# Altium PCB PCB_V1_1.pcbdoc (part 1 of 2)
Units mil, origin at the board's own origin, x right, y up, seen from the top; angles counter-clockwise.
Board outline 2047.24 x 3937.01 mil, 2 copper layers (Top Layer, Bottom Layer), stack 62.206 mil thick; 99 components, 62 nets, 329 pads, 46 vias.
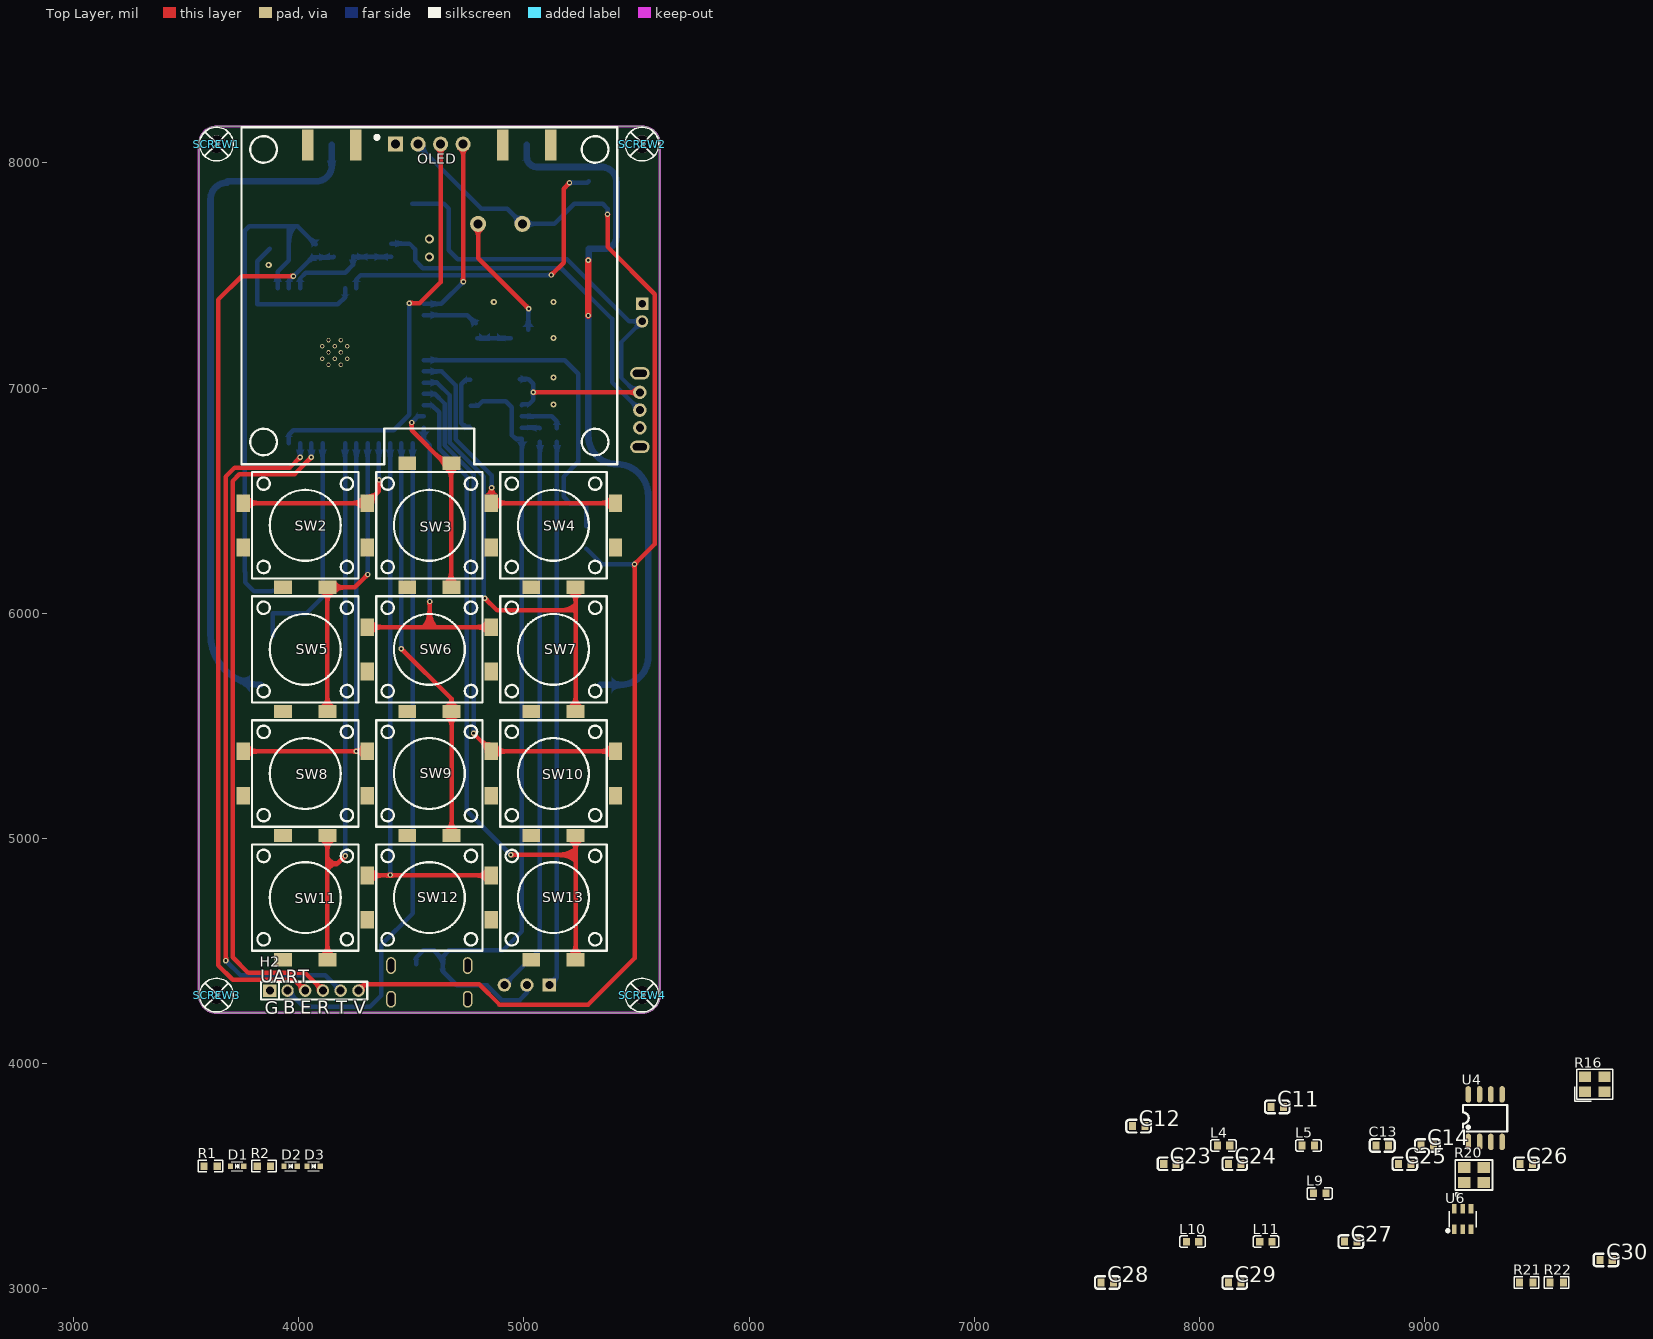
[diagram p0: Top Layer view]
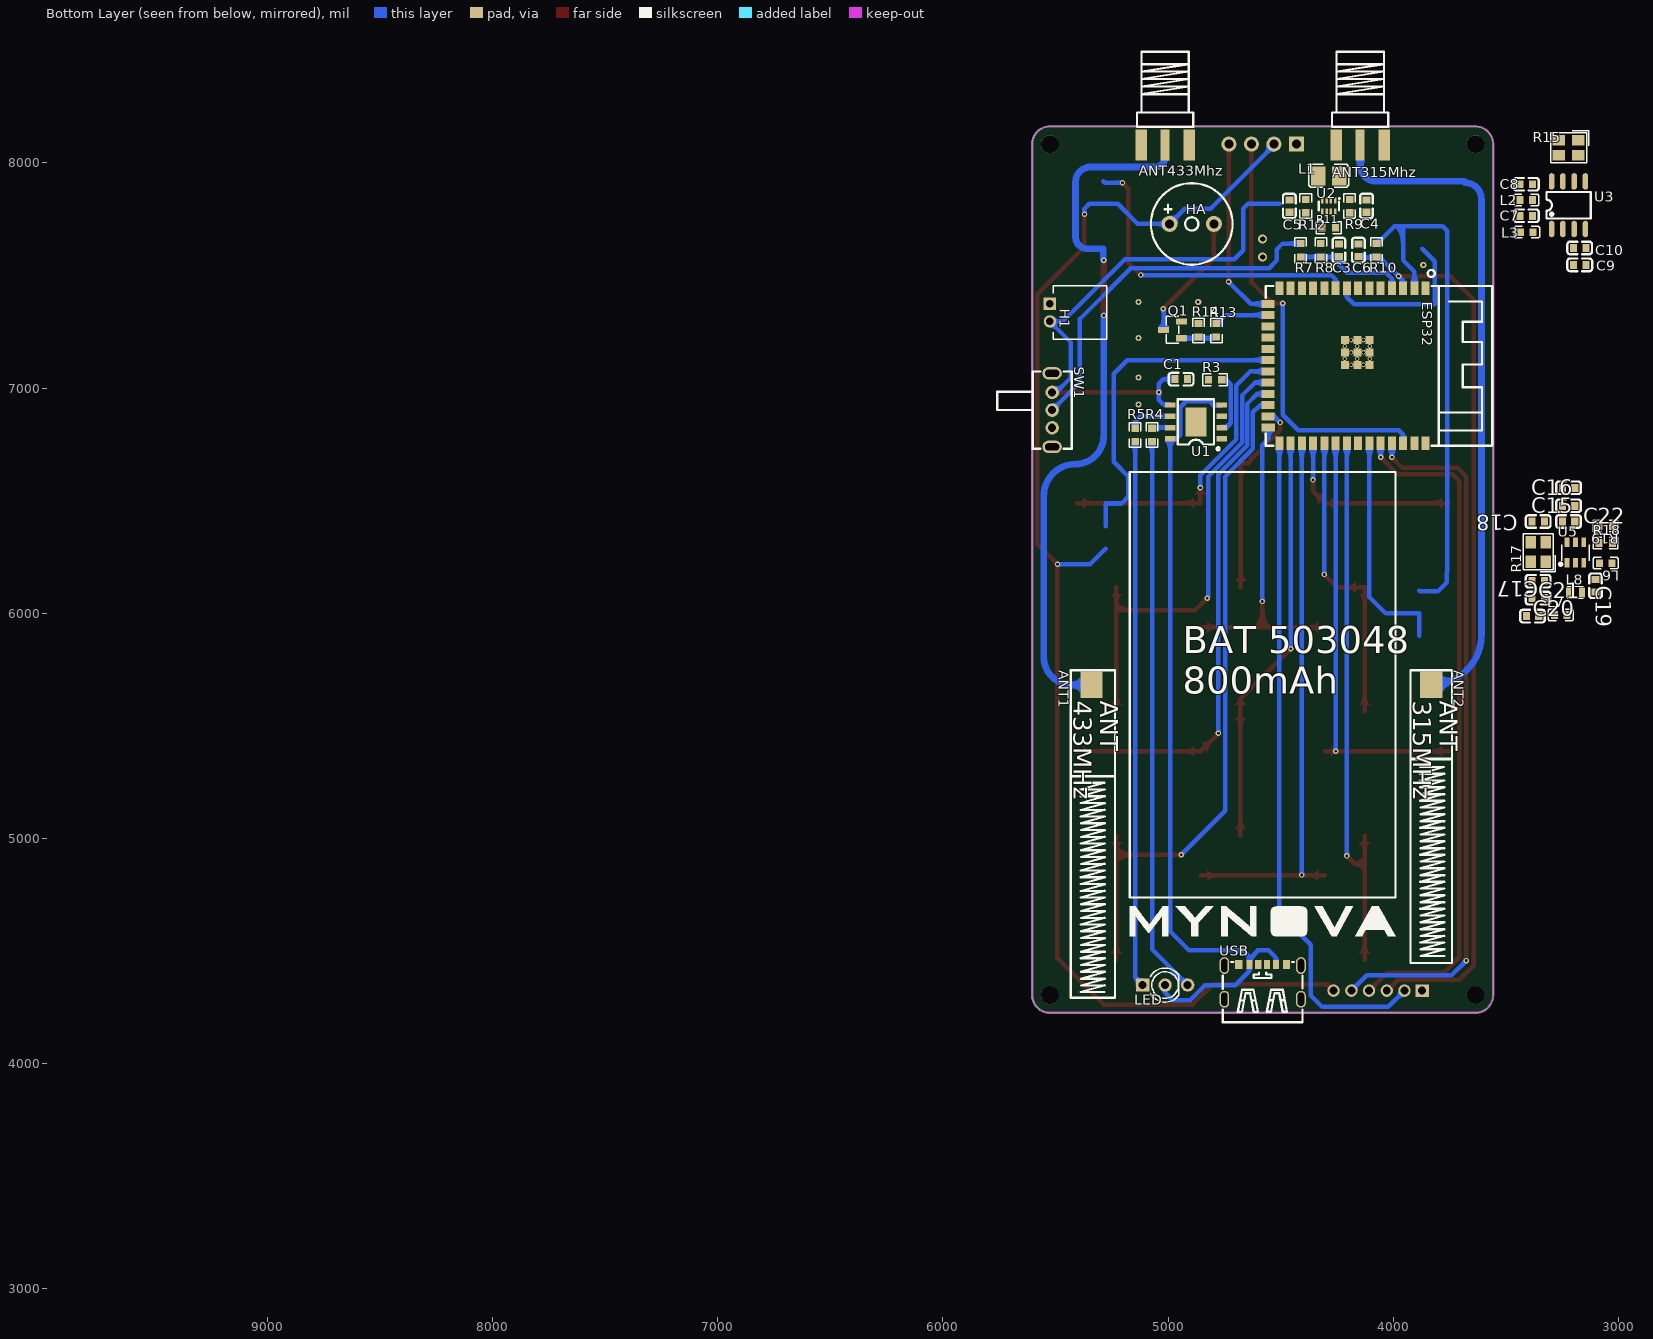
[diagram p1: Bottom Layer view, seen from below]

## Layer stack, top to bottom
Top Solder Mask Layer: solder mask 0.394, Dk 3.3
Top Layer: signal copper 1.379
Dielectric1: surface 59.449, FR4, Dk 4.5
Bottom Layer: signal copper 1.378
Bottom Solder Mask Layer: solder mask 0.394, Dk 3.3

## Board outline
3556.07,4304.21 ccw(c3634.81,4304.21) 3634.81,4225.47 5524.57,4225.47 ccw(c5524.57,4304.21) 5603.31,4304.21 5603.31,8083.74 ccw(c5524.57,8083.74) 5524.57,8162.48 3634.81,8162.48 ccw(c3634.81,8083.74) 3556.07,8083.74

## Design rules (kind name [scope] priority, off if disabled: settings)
BoardOutlineClearance copperThickness1oz [All] p0: genericclearance=10 ignorepadtopadclearanceinfootprint=FALSE except(0: Arc-SplitContinuation Track-SplitContinuation SMDPad-SplitContinuation THPad-SplitContinuation Via-SplitContinuation Fill-SplitContinuation Poly-SplitContinuation Region-SplitContinuation Text-SplitContinuation)
BoardOutlineClearance copperThickness2oz [All] p0: genericclearance=10 ignorepadtopadclearanceinfootprint=FALSE except(0: Arc-SplitContinuation Track-SplitContinuation SMDPad-SplitContinuation THPad-SplitContinuation Via-SplitContinuation Fill-SplitContinuation Poly-SplitContinuation Region-SplitContinuation Text-SplitContinuation)
BoardOutlineClearance Plane_innerPlane [All] p0: genericclearance=10 ignorepadtopadclearanceinfootprint=FALSE except(0: Arc-SplitContinuation Track-SplitContinuation SMDPad-SplitContinuation THPad-SplitContinuation Via-SplitContinuation Fill-SplitContinuation Poly-SplitContinuation Region-SplitContinuation Text-SplitContinuation)
BoardOutlineClearance Copper_copperRegion [All] p0: genericclearance=10 ignorepadtopadclearanceinfootprint=FALSE except(0: Arc-SplitContinuation Track-SplitContinuation SMDPad-SplitContinuation THPad-SplitContinuation Via-SplitContinuation Fill-SplitContinuation Poly-SplitContinuation Region-SplitContinuation Text-SplitContinuation)
BoardOutlineClearance Copper_Direct [All] p0: genericclearance=10 ignorepadtopadclearanceinfootprint=FALSE except(0: Arc-SplitContinuation Track-SplitContinuation SMDPad-SplitContinuation THPad-SplitContinuation Via-SplitContinuation Fill-SplitContinuation Poly-SplitContinuation Region-SplitContinuation Text-SplitContinuation)
BoardOutlineClearance otherClearance [All] p0: genericclearance=10 ignorepadtopadclearanceinfootprint=FALSE except(0: Arc-SplitContinuation Track-SplitContinuation SMDPad-SplitContinuation THPad-SplitContinuation Via-SplitContinuation Fill-SplitContinuation Poly-SplitContinuation Region-SplitContinuation Text-SplitContinuation)
Clearance copperThickness1oz [All] p1: gap=7 ignorepadtopadclearanceinfootprint=FALSE
Clearance copperThickness2oz [All] p1: gap=7 ignorepadtopadclearanceinfootprint=FALSE
Clearance Plane_innerPlane [All] p1: gap=7 ignorepadtopadclearanceinfootprint=FALSE
Clearance Copper_copperRegion [All] p1: gap=7 ignorepadtopadclearanceinfootprint=FALSE
Clearance Copper_Direct [All] p1: gap=7 ignorepadtopadclearanceinfootprint=FALSE
Clearance otherClearance [All] p1: gap=7 ignorepadtopadclearanceinfootprint=FALSE
DiffPairsRouting differentialPair [All] p1: maxuncoupledlength=10 minlimit=5.9843 maxlimit=Infinity mostfreqgap=5.9843 toplayer_minwidth=5 toplayer_prefwidth=10 toplayer_maxwidth=100 bottomlayer_minwidth=5 bottomlayer_prefwidth=10 bottomlayer_maxwidth=100
PasteMaskExpansion pasteMaskExpansion [All] p1: expansion=0
PlaneConnect innerPlane [All] p1: planeconnectstyle=Relief reliefexpansion=20 reliefentries=4 reliefconductorwidth=10 reliefairgap=10
PolygonConnect copperRegion [All] p1: connectstyle=Relief reliefentries=4 reliefconductorwidth=10 polygonreliefangle="90 Angle" airgapwidth=10
PolygonConnect Direct [All] p1: connectstyle=Direct reliefentries=4 reliefconductorwidth=10 polygonreliefangle="90 Angle" airgapwidth=10
RoutingVias viaSize [All] p1: viastyle="Through Hole" holewidth=12.0078 minholewidth=11.811 maxholewidth=248.0314 width=12.0078 minwidth=11.811 maxwidth=248.0314
SolderMaskExpansion solderMaskExpansion [All] p1: useseparateexpansions=TRUE expansion=2.0079 expansionbottom=2.0079
Width copperThickness1oz [All] p1: maxlimit=100 minlimit=5 preferedwidth=10
Width copperThickness2oz [All] p1: maxlimit=100 minlimit=8 preferedwidth=10

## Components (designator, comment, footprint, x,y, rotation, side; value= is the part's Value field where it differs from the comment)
ANT1 "" SMD-ANT-433 5339.53,5682.17 r270 bottom
ANT2 "" SMD-ANT-315 3831.07,5682.17 r270 bottom
ANT315Mhz "" SMA-TH_SMA-KE-P901 4146.62,8079.8 r180 bottom
ANT433Mhz "" SMA-TH_SMA-KE-P901 5012.76,8079.8 r180 bottom
C1 "" C0603 4941.92,7039.76 r180 bottom
C3 "" C0603 4241.07,7612.48 r270 bottom
C4 "" C0603 4118.56,7808.82 r90 bottom
C5 "" C0603 4461.07,7808.82 r90 bottom
C6 "" C0603 4154.4,7612.48 r270 bottom
C7 "" C0603 3408.55,7765.65 r180 bottom
C8 "" C0603 3408.55,7905.65 r180 bottom
C9 "" C0603 3171.68,7547.69 r0 bottom
C10 "" C0603 3171.68,7622.69 r0 bottom
C11 "" C0603 8345.53,3807.83 r0 top
C12 "" C0603 7730.1,3722.23 r0 top
C13 "" C0603 8812.23,3636.43 r0 top
C14 "" C0603 9012.23,3636.43 r0 top
C15 "" C0603 3221.07,6477.48 r0 bottom
C16 "" C0603 3221.07,6557.48 r0 bottom
C17 "" C0603 3356.07,6142.48 r0 bottom
C18 "" C0603 3356.07,6407.48 r0 bottom
C19 "" C0603 3101.07,6122.48 r270 bottom
C20 "" C0603 3381.07,5987.48 r180 bottom
C21 "" C0603 3356.07,6067.48 r180 bottom
C22 "" C0603 3221.07,6407.48 r180 bottom
C23 "" C0603 7869.24,3555.14 r0 top
C24 "" C0603 8157.06,3555.14 r0 top
C25 "" C0603 8912.23,3555.14 r0 top
C26 "" C0603 9451.97,3555.14 r0 top
C27 "" C0603 8672.49,3209.24 r0 top
C28 "" C0603 7590.97,3027.95 r0 top
C29 "" C0603 8157.06,3027.95 r0 top
C30 "" C0603 9805.8,3127.95 r0 top
D1 "" SOD-523_L1.2-W0.8-LS1.6-BI 3726.29,3544.64 r0 top
D2 "" SOD-523_L1.2-W0.8-LS1.6-BI 3963.39,3544.64 r0 top
D3 "" SOD-523_L1.2-W0.8-LS1.6-BI 4065.75,3544.64 r0 top
ESP32 "" WIRELM-SMD_ESP32-S3-WROOM-1 4205.67,7099.49 r270 bottom
H1 "" CONN-TH_PH-2AW_C2908634 5524.57,7335.71 r270 bottom
H2 "" 6PIN-2MM-UART 4067.88,4323.9 r0 top
HA "" BUZ-TH_BD9.0-P5.00-D0.6-FD 4894.65,7729.41 r180 bottom
L1 "" L1008 4286.07,7942.48 r180 bottom
L2 "" L0603 3408.55,7835.65 r0 bottom
L3 "" L0603 3406.07,7692.48 r180 bottom
L4 "" L0603 8107.06,3636.43 r0 top
L5 "" L0603 8484.01,3636.43 r0 top
L6 "" L0603 3056.07,6222.48 r0 bottom
L7 "" L0603 3256.07,5992.48 r180 bottom
L8 "" IND-SMD_L1.8-W1.1 3191.07,6092.48 r180 bottom
L9 "" L0603 8534.01,3423.91 r0 top
L10 "" L0603 7969.24,3209.24 r0 top
L11 "" L0603 8295.53,3209.24 r0 top
LED "" LED-TH_3P-BD3.8-P2.54-BI 5012.76,4348.9 r180 bottom
OLED "" OLED-TH_-4P-L42.4-W38.0-P2.54 4579.69,8083.74 r0 top
Q1 "" SOT-23-3_L2.9-W1.3-P1.90-LS2.4-BR 4980.01,7258.86 r180 bottom
R1 "" R0603 3607.73,3544.64 r0 top
R2 "" R0603 3844.84,3544.64 r0 top
R3 "" R0603 4791.07,7037.48 r180 bottom
R4 "" R0603 5071.07,6792.48 r90 bottom
R5 "" R0603 5146.07,6792.48 r90 bottom
R7 "" R0603 4411.07,7612.48 r90 bottom
R8 "" R0603 4321.07,7612.48 r270 bottom
R9 "" R0603 4193.56,7808.82 r90 bottom
R10 "" R0603 4074.4,7612.48 r270 bottom
R11 "" R0603 4286.07,7712.48 r180 bottom
R12 "" R0603 4388.56,7808.82 r90 bottom
R13 "" R0603 4785.09,7256.97 r270 bottom
R14 "" R0603 4864.37,7256.97 r90 bottom
R15 "" CRYSTAL-SMD_4P-L3.2-W2.5-BL 3221.07,8067.48 r0 bottom
R16 "" CRYSTAL-SMD_4P-L3.2-W2.5-BL 9755.8,3907.83 r0 top
R17 "" CRYSTAL-SMD_4P-L3.2-W2.5-BL 3356.07,6272.48 r90 bottom
R18 "" R0603 3056.07,6312.48 r180 bottom
R19 "" R0603 3056.07,6387.48 r0 bottom
R20 "" CRYSTAL-SMD_4P-L3.2-W2.5-BL_SIT8008BI 9219.14,3505.14 r0 top
R21 "" R0603 9451.97,3027.95 r0 top
R22 "" R0603 9586.71,3027.95 r0 top
SCREW1 "" M2螺丝 3634.81,8083.74 r0 top
SCREW2 "" M2螺丝 5524.57,8083.74 r0 top
SCREW3 "" M2螺丝 3634.81,4304.21 r0 top
SCREW4 "" M2螺丝 5524.57,4304.21 r0 top
SW1 "" SW-TH_SK12D07VG4 5514.57,6902.64 r270 bottom
SW2 "" SW-SMD_4P-L12.0-W12.0-P5.00-LS15.4 4028.51,6390.83 r0 top
SW3 "" SW-SMD_4P-L12.0-W12.0-P5.00-LS15.4 4579.69,6390.83 r270 top
SW4 "" SW-SMD_4P-L12.0-W12.0-P5.00-LS15.4 5130.87,6390.83 r0 top
SW5 "" SW-SMD_4P-L12.0-W12.0-P5.00-LS15.4 4028.51,5839.65 r270 top
SW6 "" SW-SMD_4P-L12.0-W12.0-P5.00-LS15.4 4579.69,5839.65 r0 top
SW7 "" SW-SMD_4P-L12.0-W12.0-P5.00-LS15.4 5130.87,5839.65 r270 top
SW8 "" SW-SMD_4P-L12.0-W12.0-P5.00-LS15.4 4028.51,5288.46 r0 top
SW9 "" SW-SMD_4P-L12.0-W12.0-P5.00-LS15.4 4579.69,5288.46 r270 top
SW10 "" SW-SMD_4P-L12.0-W12.0-P5.00-LS15.4 5130.87,5288.46 r0 top
SW11 "" SW-SMD_4P-L12.0-W12.0-P5.00-LS15.4 4028.51,4737.28 r270 top
SW12 "" SW-SMD_4P-L12.0-W12.0-P5.00-LS15.4 4579.69,4737.28 r0 top
SW13 "" SW-SMD_4P-L12.0-W12.0-P5.00-LS15.4 5130.87,4737.28 r270 top
U1 "" ESOP-8_L4.9-W3.9-P1.27-LS6.0-BL-EP 4876.02,6849.76 r90 bottom
U2 "" SOT-583-8_L2.1-W1.2-P0.50-LS1.6-BL 4286.07,7808.82 r0 bottom
U3 "" SOP-8_L4.9-W3.9-P1.27-LS6.0-BL 3221.07,7812.48 r180 bottom
U4 "" SOP-8_L4.9-W3.9-P1.27-LS6.0-BL 9269.14,3757.83 r0 top
U5 "" SOT-23-6_L2.9-W1.6-P0.95-LS2.8-BL 3190.62,6269.24 r180 bottom
U6 "" SOT-23-6_L2.9-W1.6-P0.95-LS2.8-BL 9169.14,3309.24 r0 top
USB "" TYPE-C-SMD_TYPE-C-6P 4579.69,4363.27 r180 bottom

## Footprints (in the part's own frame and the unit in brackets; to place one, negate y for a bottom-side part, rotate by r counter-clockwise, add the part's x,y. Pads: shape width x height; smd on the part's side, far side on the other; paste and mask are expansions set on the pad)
6PIN-2MM-UART [mm]
  round 1.4 hole 0.9: BOOT(-3,0) EN(-1,0) RXD(1,0) TXD(3,0) VCC(5,0)
  rect 1.524x1.4 hole 0.9: GND(-5,0)
  silkscreen extent -6,-1 6,1.02
BUZ-TH_BD9.0-P5.00-D0.6-FD [mm]
  round 1.8 hole 1 copper offset 0,0: 1(-2.5,0)
  round 1.8 hole 1: 2(2.5,0)
  silkscreen extent -4.6,-4.6 4.6,4.6
C0603 [mm]
  rect 0.8x0.9 smd: 1(-0.7,0) 2(0.7,0)
  silkscreen extent -1.41,-0.71 1.39,0.72
CONN-TH_PH-2AW_C2908634 [mm]
  rect 1.4x1.4 hole 0.85: 1(-1,0)
  round 1.4 hole 0.85: 2(1,0)
  silkscreen extent -3,0.4 3,6.4
CRYSTAL-SMD_4P-L3.2-W2.5-BL [mm]
  rect 1.4x1.2 smd: 1(-1.1,-0.85) 2(1.1,-0.85) 3(1.1,0.85) 4(-1.1,0.85)
  silkscreen extent -2.26,-1.91 2.03,1.68
CRYSTAL-SMD_4P-L3.2-W2.5-BL_SIT8008BI [mm]
  rect 1.4x1.2 smd: 1(-1.1,-0.85) 2(1.1,-0.85) 3(1.1,0.85) 4(-1.1,0.85)
  silkscreen extent -2.1,-2.35 2.1,1.7
ESOP-8_L4.9-W3.9-P1.27-LS6.0-BL-EP [mm]
  rect 0.6x1.2 smd: 1(-1.905,-2.908) 2(-0.635,-2.908) 3(0.635,-2.908) 4(1.905,-2.908) 5(1.905,2.908) 6(0.635,2.908) 7(-0.635,2.908) 8(-1.905,2.908)
  rect 3.3x2.4 smd: 9(0,0)
  silkscreen extent -3.2,-2.67 2.55,2.05
IND-SMD_L1.8-W1.1 [mm]
  rect 0.64x1.1 smd: 1(-0.75,0) 2(0.75,0)
  silkscreen extent -0.9,-0.71 0.9,0.71
L0603 [mm]
  rect 0.8x0.864 smd: 1(-0.7,0) 2(0.7,0)
  silkscreen extent -1.42,-0.65 1.42,0.65
L1008 [mm]
  rect 1.635x2.16 smd: 1(-1.168,0) 2(1.168,0)
  silkscreen extent -2.27,-1.27 2.27,1.3
LED-TH_3P-BD3.8-P2.54-BI [mm]
  rect 1.5x1.5 hole 0.9: 1(-2.54,0)
  round 1.5 hole 0.9: 2(0,0) 3(2.54,0)
  silkscreen extent -1.7,-1.92 1.54,1.92
M2螺丝 [mm]
  round 2 hole 2: 1(0,0)
  silkscreen extent -1.9,-1.9 1.9,1.9
OLED-TH_-4P-L42.4-W38.0-P2.54 [mm]
  rect 1.7x1.7 hole 1: 1(-3.81,0)
  round 1.7 hole 1: 2(-1.27,0) 3(1.27,0) 4(3.81,0)
  silkscreen extent -21.2,-36.1 21.2,1.91
R0603 [mil]
  rect 31.75x34.02 smd: 1(-29.66,0) 2(29.66,0)
  silkscreen extent -55,-26 55,26
SMA-TH_SMA-KE-P901 [mm]
  rect 1.3x3.5 smd: 1(-2.7,0) 2(2.7,0)
  rect 1.3x3.5 smd far side: 3(-2.7,0) 4(2.7,0)
  rect 1x3.5 smd: 5(0,0)
  silkscreen extent -3.17,2.03 3.18,10.53
SMD-ANT-315 [mm]
  rect 3x2.5 smd: 1(0,0)
  silkscreen extent -1.65,-2.35 31.38,2.35
SMD-ANT-433 [mm]
  rect 3x2.5 smd: 1(0,0)
  silkscreen extent -1.65,-2.35 35.29,2.65
SOD-523_L1.2-W0.8-LS1.6-BI [mm]
  rect 0.6x0.6 smd: 1(-0.75,0) 2(0.75,0)
  silkscreen extent -0.65,-0.5 0.65,0.5
SOP-8_L4.9-W3.9-P1.27-LS6.0-BL [mm]
  oval 0.63x1.865 smd: 1(-1.905,-2.682) 2(-0.635,-2.682) 3(0.635,-2.682) 4(1.905,-2.682) 5(1.905,2.682) 6(0.635,2.682) 7(-0.635,2.682) 8(-1.905,2.682)
  silkscreen extent -2.5,-1.5 2.5,1.48
SOT-23-3_L2.9-W1.3-P1.90-LS2.4-BR [mm]
  rect 1.25x0.7 smd: 1(1,-0.95) 2(1,0.95) 3(-1,0)
  silkscreen extent -0.73,-1.53 0.73,1.53
SOT-23-6_L2.9-W1.6-P0.95-LS2.8-BL [mil]
  rect 20.95x42.2 smd: 1(-37.4,-45.24) 2(0,-45.24) 3(37.4,-45.24) 4(37.4,45.24) 5(0,45.24) 6(-37.4,45.24)
  silkscreen extent -72,-57 61,35
SOT-583-8_L2.1-W1.2-P0.50-LS1.6-BL [mm]
  rect 0.28x0.68 smd: 1(-0.75,-0.64) 2(-0.25,-0.64) 3(0.25,-0.64) 4(0.75,-0.64) 5(0.75,0.64) 6(0.25,0.64) 7(-0.25,0.64) 8(-0.75,0.64)
  silkscreen extent -1.27,-0.93 1.14,0.51
SW-SMD_4P-L12.0-W12.0-P5.00-LS15.4 [mm]
  rect 1.5x2 smd: 1(-7,2.5) 2(7,2.5) 3(-7,-2.5) 4(7,-2.5)
  silkscreen extent -6,-6 6,6
SW-TH_SK12D07VG4 [mil]
  round 60 hole 36: 1(-78.74,0) 2(0,0) 3(78.74,0)
  oval 55.12x86.61 hole 31.5 slot 62.99 at 90 deg: 4(163.38,0) 5(-163.39,0)
  silkscreen extent -171,-244 171,87
TYPE-C-SMD_TYPE-C-6P [mm]
  oval 1.1x1.9 hole 0.7 slot 1.5 at 90 deg: 7(-4.32,-1.963) 7(-4.32,1.838) 7(4.32,-1.963) 7(4.32,1.838)
  rect 0.7x1 smd: A5(-0.5,1.963) A9(1.5,1.963) B5(0.5,1.963) B9(-1.5,1.963)
  rect 0.8x1 smd: A12(2.7,1.963) B12(-2.7,1.963)
  silkscreen extent -4.5,-4.56 4.5,2.24
WIRELM-SMD_ESP32-S3-WROOM-1 [mm]
  rect 1.5x0.9 smd: 1(-8.75,8.895) 2(-8.75,7.625) 3(-8.75,6.355) 4(-8.75,5.085) 5(-8.75,3.815) 6(-8.75,2.545) 7(-8.75,1.275) 8(-8.75,0.005) 9(-8.75,-1.265) 10(-8.75,-2.535) 11(-8.75,-3.805) 12(-8.75,-5.075) 13(-8.75,-6.345) 14(-8.75,-7.615) 27(8.75,-7.615) 28(8.75,-6.345) 29(8.75,-5.075) 30(8.75,-3.805) 31(8.75,-2.535) 32(8.75,-1.265) 33(8.75,0.005) 34(8.75,1.275) 35(8.75,2.545) 36(8.75,3.815) 37(8.75,5.085) 38(8.75,6.355) 39(8.75,7.625) 40(8.75,8.895)
  rect 0.9x1.5 smd: 15(-6.985,-8.895) 16(-5.715,-8.895) 17(-4.445,-8.895) 18(-3.175,-8.895) 19(-1.905,-8.895) 20(-0.635,-8.895) 21(0.635,-8.895) 22(1.905,-8.895) 23(3.175,-8.895) 24(4.445,-8.895) 25(5.715,-8.895) 26(6.985,-8.865)
  rect 0.9x0.9 smd: 41(-2.9,-0.225) 41(-2.9,1.175) 41(-2.9,2.575) 41(-1.5,-0.225) 41(-1.5,1.175) 41(-1.5,2.575) 41(-0.1,-0.225) 41(-0.1,1.175) 41(-0.1,2.575)
  silkscreen extent -10.82,-9.14 9.02,16.39

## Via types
v1: diameter 24.02, hole 12.01, Top Layer to Bottom Layer, 26 vias
v2: diameter 19.69, hole 11.81, Top Layer to Bottom Layer, 12 vias
v3: diameter 27.56, hole 13.78, Top Layer to Bottom Layer, 6 vias
v4: diameter 39.37, hole 23.62, Top Layer to Bottom Layer, 2 vias

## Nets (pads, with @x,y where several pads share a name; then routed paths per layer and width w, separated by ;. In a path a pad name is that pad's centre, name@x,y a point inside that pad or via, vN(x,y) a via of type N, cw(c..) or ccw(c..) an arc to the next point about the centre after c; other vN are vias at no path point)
315_RX: ESP32.35 U3.5 | length 1034.9
  Bottom Layer w20: 3883.37,5900.27 3883.37,6000.27 4033.86,6000.27 4105.48,6071.89 ESP32.35@4105.48,6755
315_TX: ESP32.34 | length 711.2
  Bottom Layer w20: 3871.03,7618.78 3816.07,7563.83 3816.07,7372.48 4173.51,7372.48 4205.48,7404.45 4205.48,7443.98
315ANT: ANT2.1 ANT315Mhz.5 C7.1 C8.1 C20.2 L2.2 L7.1 | length 3000.1
  Bottom Layer w29.53: ANT2.1@3831.07,5682.17 cw(c3831.07,5905.49) 3607.74,5905.49 3607.74,7839.15 cw(c3681.07,7839.15) 3681.07,7912.48 cw(c3687.37,7912.48) 3687.37,7918.78 4077.37,7918.78 ccw(c4077.37,7987.48) 4146.07,7987.48 4146.07,8079.25 cw(c4146.62,8079.25) ANT315Mhz.5@4146.62,8079.8
433_RX: ESP32.20 U4.5 | length 1496.3
  Bottom Layer w20: ESP32.20@4555.87,7124.49 5181.07,7124.49 5241.07,7064.49 5241.07,6672.48 5176.07,6607.48 5176.07,6517.48 5205.87,6487.68 5276.01,6487.68 5276.01,6387.68
433_TX: ESP32.21 | length 1444.7
  Top Layer w20: v1(5121.07,7502.48) 5176.07,7557.48 5176.07,7886.31 v1(5202.23,7912.48)
  Bottom Layer w20: 4255.48,7443.98 4255.48,7482.48 4275.48,7502.48 v1(5121.07,7502.48) ; v1(5202.23,7912.48) 5282.06,7912.48 5288.35,7918.78
433ANT: ANT1.1 ANT433Mhz.5 C11.2 C12.1 C28.1 L4.2 L10.1 | length 3159.4
  Top Layer w29.53: v1(5286.07,7322.48) v1(5286.07,7567.48)
  Bottom Layer w29.53: ANT433Mhz.5@5012.76,8079.8 5012.76,8025.79 ccw(c5056.07,8025.79) 5056.07,7982.48 5343.23,7982.48 cw(c5343.23,7914.64) 5411.07,7914.64 5411.07,7672.48 cw(c5357.36,7672.48) 5357.36,7618.78 5288.35,7618.78 5288.35,7569.77 v1(5286.07,7567.48) ; v1(5286.07,7322.48) 5286.07,6787.48 ccw(c5411.07,6787.48) 5411.07,6662.48 cw(c5411.07,6521.91) 5551.64,6521.91 5551.64,5805.91 cw(c5427.9,5805.91) 5427.9,5682.17 ANT1.1@5339.53,5682.17
$1N804: U1.2 | length 270.1
  Bottom Layer w20: 4761.41,7037.48 4741.07,7037.48 4721.07,7017.48 4721.07,6844.76 4741.07,6824.76 U1.2@4761.52,6824.76
$1N6847: U1.7 | length 81.6
  Bottom Layer w20: U1.7@4990.52,6824.76 5068.45,6824.76 5071.07,6822.14
$1N7056: LED.1 | length 2427.7
  Bottom Layer w20: LED.1@5112.76,4348.9 5146.07,4382.2 5146.07,6762.82
$1N7064: U1.6 | length 195.1
  Bottom Layer w20: U1.6@4990.52,6874.76 5123.79,6874.76 5146.07,6852.48 5146.07,6822.14
$1N11631: LED.3 | length 2479.5
  Bottom Layer w20: LED.3@4912.76,4348.9 5071.07,4507.2 5071.07,6762.82
$1N15750: HA.2 Q1.3 | length 564.4
  Top Layer w20: HA.2@4796.23,7729.41 4796.22,7577.32 v1(5021.07,7352.48)
  Bottom Layer w20: Q1.3@5019.38,7258.86 5019.38,7350.79 v1(5021.07,7352.48)
$1N15783: Q1.1 | length 148.1
  Bottom Layer w20: 4792.49,7221.46 Q1.1@4940.64,7221.46
$1N28849: D2.1 R2.1 USB.B5
$1N28850: D1.1 R1.1 USB.A5
$1N28865: R9.1 R11.2 U2.8
$1N28870: L1.2 U2.2
$1N28871: L1.1 U2.3
$1N28873: U2.5 U2.6
$2N3: R22.2 U6.4
$2N4: R19.2 U5.4
$2N9: C18.2 R17.3 U5.6
$2N10: C26.2 R20.3 U6.6
$2N13: C25.1 R20.1 U6.1
$2N14: C17.1 R17.1 U5.1
$2N23: C29.1 L10.2 L11.1
$2N24: C21.2 L7.2 L8.1
$2N25: C19.2 L8.2
$2N26: C27.2 L11.2
$2N27: C27.1 L9.2 U6.3
$2N28: C19.1 L6.2 U5.3
$2N38: C7.2 L3.2 U3.2
$2N39: C11.1 L5.2 U4.2
$2N57: R16.3 U4.8
$2N58: R15.3 U3.8
$2N59: R16.1 U4.7
$2N60: R15.1 U3.7
+3.3V: C4.2 C9.2 C10.2 C13.2 C14.2 C15.1 C16.1 C22.2 C23.1 C24.1 C30.2 ESP32.2 H2.VCC HA.1 L6.1 L9.1 OLED.2 R9.2 U2.1 U3.3 U4.3 U5.5 U6.5 | length 8452.2
  Top Layer w20: H2.VCC@4264.73,4323.9 4293.31,4352.48 4801.07,4352.48 4891.07,4262.48 5286.07,4262.48 5491.07,4467.48 v1(5491.07,6217.48) 5581.07,6307.48 5581.07,7417.48 5371.07,7627.48 v1(5371.07,7772.48)
  Bottom Layer w19.68: 3947.54,7718.78 3994.35,7718.78 4073.27,7639.86 4074.4,7639.86
  Bottom Layer w20: 3883.37,6100.27 3880.58,6097.48 3801.07,6097.48 3761.07,6137.48 3761.07,6182.48 3759.89,6183.66 3759.89,7698.78 3779.89,7718.78 3947.54,7718.78 3956.07,7710.26 3956.07,7567.48 3905.48,7516.89 ESP32.2@3905.48,7443.98 ; OLED.2@4529.69,8083.74 4529.69,8078.86 4811.07,7797.48 4925,7797.48 HA.1@4993.09,7729.41 5133.87,7729.41 5223.23,7818.78 5349.77,7818.78 5371.07,7797.48 v1(5371.07,7772.48) ; 5276.01,6287.68 5346.21,6217.48 v1(5491.07,6217.48)
ADC: C3.2 ESP32.39 | length 511.9
  Bottom Layer w19.68: 4005.48,7443.98 4005.48,7486.89 4031.07,7512.48 4206.07,7512.48 4241.07,7547.48 C3.2@4241.07,7584.92 4243.17,7582.82 4321.07,7582.82 4411.07,7582.82
B+: C1.1 H1.2 SW1.1 U1.5 | length 2418
  Top Layer w20: v1(5041.07,6981.38) SW1.1@5514.57,6981.38
  Bottom Layer w19.68: 4504.02,7819.83 4643.72,7819.83 4666.07,7797.48 4666.07,7612.48 4706.07,7572.48 5191.07,7572.48 5467.21,7296.34 H1.2@5524.57,7296.34
  Bottom Layer w20: C1.1@4981.29,7039.76 5021.07,7039.76 5041.07,7019.76 v1(5041.07,6981.38) 5041.07,6947.48 5021.07,6927.48 4993.24,6927.48 U1.5@4990.52,6924.76 ; SW1.1@5514.57,6981.38 5497.17,6981.38 5431.07,7047.48 5431.07,7202.84 H1.2@5524.57,7296.34
BOOT: ESP32.27 H2.BOOT | length 2976.9
  Bottom Layer w20: H2.BOOT@3949.77,4323.9 4021.19,4252.48 4316.07,4252.48 4366.07,4302.48 4366.07,4527.48 4505.48,4666.89 ESP32.27@4505.48,6755
BUZZER: ESP32.16 | length 244.3
  Bottom Layer w20: ESP32.16@4555.87,7324.49 4748.78,7324.49 4785.09,7288.18
EN: C6.2 ESP32.3 H2.EN | length 4043.6
  Top Layer w20: v1(3976.07,7497.48) 3746.07,7497.48 3641.07,7392.48 3641.07,4437.48 3706.07,4372.48 3979.93,4372.48 H2.EN@4028.51,4323.9
  Bottom Layer w19.68: v1(3976.07,7497.48) 4059.13,7580.54 4074.4,7580.54
  Bottom Layer w20: ESP32.3@3955.48,7443.98 3955.48,7476.89 v1(3976.07,7497.48) ; 4074.4,7580.54 4152.3,7580.54 C6.2@4154.4,7582.64
GND: ANT315Mhz.1 ANT315Mhz.2 ANT315Mhz.3 ANT315Mhz.4 ANT433Mhz.1 ANT433Mhz.2 ANT433Mhz.3 ANT433Mhz.4 C1.2 C3.1 C4.1 C5.1 C6.1 C8.2 C9.1 C10.1 C12.2 C13.1 C14.1 C15.2 C16.2 C17.2 C18.1 C20.1 C21.1 C22.1 C23.2 C24.2 C25.2 C26.1 C28.2 C29.2 C30.1 D1.2 D2.2 D3.2 ESP32.1 ESP32.40 ESP32.41 H1.1 H2.GND L2.1 L3.1 L4.1 L5.1 OLED.1 Q1.2 R1.2 R2.2 R11.1 R15.2 R15.4 R16.2 R16.4 R17.2 R17.4 R19.1 R20.2 R20.4 R22.1 SW1.5 SW2.3 SW2.4 SW3.3 SW3.4 SW4.3 SW4.4 SW5.3 SW5.4 SW6.3 SW6.4 SW7.3 SW7.4 SW8.3 SW8.4 SW9.3 SW9.4 SW10.3 SW10.4 SW11.3 SW11.4 SW12.3 SW12.4 SW13.3 SW13.4 U1.1 U1.3 U1.9 U2.7 U3.1 U3.4 U3.6 U4.1 U4.4 U4.6 U5.2 U6.2 USB.7 USB.A12 USB.B12
  other v2: 4131.86,7103.43 4186.98,7103.43 4104.3,7130.99 4159.42,7130.99 4214.54,7130.99 4131.86,7158.55 4186.98,7158.55 4104.3,7186.11 4159.42,7186.11 4214.54,7186.11 4131.86,7213.67 4186.98,7213.67
  other v3: 5131.07,6927.48 5130.87,7047.48 5130.87,7222.48 4866.07,7382.48 5130.87,7382.48 3866.07,7547.48
  other v4: 4579.69,7582.48 4579.69,7662.48
I2C_SCL: ESP32.38 OLED.3 | length 1895.4
  Top Layer w20: v1(4491.07,7377.48) 4536.07,7377.48 4629.69,7471.1 OLED.3@4629.69,8083.74
  Bottom Layer w20: ESP32.38@3955.48,6755 3955.48,6792.48 3975.48,6812.48 4421.07,6812.48 4491.07,6882.48 v1(4491.07,7377.48)
I2C_SDA: ESP32.15 OLED.4 | length 827.6
  Top Layer w20: OLED.4@4729.69,8083.74 4729.69,7473.86 v1(4731.07,7472.48)
  Bottom Layer w20: ESP32.15@4555.87,7374.49 4633.07,7374.49 v1(4731.07,7472.48)
KEY_1: ESP32.14 SW5.1 SW5.2 | length 1336.8
  Top Layer w20: SW5.2@4126.93,5564.06 SW5.1@4126.93,6115.24 4248.82,6115.24 v1(4306.07,6172.48)
  Bottom Layer w20: 4305.48,6755 4305.48,6173.07 v1(4306.07,6172.48)
KEY_2: ESP32.13 SW6.1 SW6.2 | length 1450.6
  Top Layer w20: SW6.1@4304.1,5938.07 4586.07,5938.07 ; v1(4581.07,6052.48) 4581.07,5943.07 4586.07,5938.07 ; SW6.2@4855.28,5938.07 4586.07,5938.07
  Bottom Layer w20: 4554.69,6824.49 4554.69,6773.86 4581.07,6747.48 v1(4581.07,6052.48)
KEY_3: ESP32.12 SW7.1 SW7.2 | length 2083.7
  Top Layer w20: v1(4826.07,6067.48) 4881.07,6012.48 5220.76,6012.48 5229.3,6003.94 ; SW7.2@5229.3,5564.06 5229.3,6003.94 ; SW7.1@5229.3,6115.24 5229.3,6003.94
  Bottom Layer w20: 4555.87,7024.49 4614.06,7024.49 4671.07,6967.48 4671.07,6757.48 4821.07,6607.48 4821.07,6072.48 v1(4826.07,6067.48)
KEY_4: ESP32.11 SW8.1 SW8.2 | length 1919.5
  Top Layer w20: SW8.1@3752.92,5386.89 v1@4256.07,5386.89 ; v1(4255.48,5387.48) v1@4256.07,5386.89 ; SW8.2@4304.1,5386.89 v1@4256.07,5386.89
  Bottom Layer w20: v1(4255.48,5387.48) 4255.48,6755
KEY_5: ESP32.10 SW9.1 SW9.2 | length 1834.3
  Top Layer w20: v1(4455.48,5842.48) 4678.11,5619.84 SW9.1@4678.11,5564.06 SW9.2@4678.11,5012.87
  Bottom Layer w20: v1(4455.48,5842.48) 4455.48,6755
KEY_6: ESP32.9 SW10.1 SW10.2 | length 2291
  Top Layer w20: v1(4776.07,5467.48) 4776.07,5466.1 SW10.1@4855.28,5386.89 SW10.2@5406.46,5386.89
  Bottom Layer w20: 4555.87,6974.49 4604.06,6974.49 4647.07,6931.48 4647.07,6746.48 4776.07,6617.48 v1(4776.07,5467.48)
KEY_7: ESP32.8 SW11.1 SW11.2 | length 2477.3
  Top Layer w20: SW11.2@4126.93,4461.69 4126.93,4887.48 ; SW11.1@4126.93,5012.87 4126.93,4887.48 ; v1(4206.07,4922.48) 4171.07,4887.48 4126.93,4887.48
  Bottom Layer w20: v1@4205.48,4922.48 4205.48,6755
KEY_8: ESP32.7 SW12.1 SW12.2 | length 2468.9
  Top Layer w20: SW12.1@4304.1,4835.71 SW12.2@4855.28,4835.71
  Bottom Layer w20: 4405.48,6755 4406.07,6754.41 v1(4406.07,4837.48)
KEY_9: ESP32.17 SW13.1 SW13.2 | length 3016.8
  Top Layer w20: v1(4941.07,4927.48) 5228.9,4927.48 5229.3,4927.08 ; SW13.2@5229.3,4461.69 5229.3,4927.08 ; SW13.1@5229.3,5012.87 5229.3,4927.08
  Bottom Layer w20: 4555.87,6924.49 4591.07,6924.49 4623.07,6892.49 4623.07,6730.48 4746.07,6607.48 4746.07,5122.48 v1(4941.07,4927.48)
KEY_BACK: ESP32.6 SW2.1 SW2.2 | length 838.7
  Top Layer w20: SW2.1@3752.92,6489.25 SW2.2@4304.1,6489.25 4356.07,6541.22 v1(4356.07,6592.48)
  Bottom Layer w20: 4355.48,6755 4356.07,6754.41 v1(4356.07,6592.48)
KEY_ENTER: ESP32.4 SW4.1 SW4.2 | length 1306.9
  Top Layer w20: v1(4856.07,6557.48) 4856.07,6490.04 SW4.1@4855.28,6489.25 SW4.2@5406.46,6489.25
  Bottom Layer w20: 4555.87,7074.49 4634.06,7074.49 4696.07,7012.48 4696.07,6772.48 4856.07,6612.48 v1(4856.07,6557.48)
KEY_MENU: ESP32.5 SW3.1 SW3.2 | length 891.4
  Top Layer w20: v1(4501.07,6847.48) 4501.07,6812.48 4647.13,6666.42 SW3.1@4678.11,6666.42 4676.07,6664.37 4676.07,6117.28 SW3.2@4678.11,6115.24
  Bottom Layer w20: v1(4501.07,6847.48) 4528.07,6874.49 4555.87,6874.49
RXD: ESP32.36 H2.RXD | length 3033.5
  Top Layer w20: v1(4055.48,6692.48) 3981.07,6618.07 3981.07,6617.48 3736.07,6617.48 3706.07,6587.48 3706.07,4472.48 3776.07,4402.48 4028.67,4402.48 H2.RXD@4107.25,4323.9
  Bottom Layer w20: v1(4055.48,6692.48) ESP32.36@4055.48,6755
TXD: ESP32.37 H2.TXD | length 3142.4
  Top Layer w20: v1(3676.07,4457.48) 3676.07,6607.48 3716.07,6647.48 3960.48,6647.48 v1(4005.48,6692.48)
  Bottom Layer w20: v1(3676.07,4457.48) 3741.07,4392.48 4117.41,4392.48 H2.TXD@4185.99,4323.9 ; v1(4005.48,6692.48) ESP32.37@4005.48,6755
VBUS: D3.1 LED.2 U1.4 U1.8 USB.A9 USB.B9 | length 3703.9
  Bottom Layer w20: USB.A9@4520.63,4440.53 4520.63,4470.22 4552.9,4502.48 4601.07,4502.48 4638.74,4464.8 USB.B9@4638.74,4440.53 ; U1.4@4763.8,6922.48 4796.07,6922.48 4816.07,6942.48 4919.27,6942.48 4946.07,6915.68 4946.07,6791.56 4962.87,6774.76 U1.8@4990.52,6774.76 4991.07,6774.22 4991.07,4587.48 4906.07,4502.48 4666.07,4502.48 4641.07,4477.48 4641.07,4442.86 USB.B9@4638.74,4440.53 ; LED.2@5012.76,4348.9 5012.76,4314.17 4981.07,4282.48 4901.07,4282.48 4836.07,4347.48 4702.11,4347.48 4638.74,4410.85 USB.B9@4638.74,4440.53
VCC: C5.2 SW1.2 U2.4 | length 1603.9
  Bottom Layer w20: 4411.07,7642.14 4491.41,7642.14 4516.07,7617.48 4516.07,7567.48 4551.07,7532.48 5166.07,7532.48 5391.07,7307.48 5391.07,7026.14 SW1.2@5514.57,6902.64
pads on no net: ESP32.18 ESP32.19 ESP32.22 ESP32.23 ESP32.24 ESP32.25 ESP32.26 ESP32.28 ESP32.29 ESP32.30 ESP32.31 ESP32.32 ESP32.33 R3.1 R3.2 R4.1 R4.2 R5.1 R5.2 R7.1 R7.2 R8.1 R8.2 R10.1 R10.2 R12.1 R12.2 R13.1 R13.2 R14.1 R14.2 R18.1 R18.2 R21.1 R21.2 SCREW1.1 SCREW2.1 SCREW3.1 SCREW4.1 SW1.3 SW1.4

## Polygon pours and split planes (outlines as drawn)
GND on Top Layer (solid, remove dead copper, pour order 0): 3556.07,8162.48 5603.31,8162.48 5603.31,4225.47 3556.07,4225.47
GND on Bottom Layer (solid, remove dead copper, pour order 2): 3556.07,8162.48 5603.31,8162.48 5603.31,4225.47 3556.07,4225.47

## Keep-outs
Board Outline Layer:
  the board outline again, w10

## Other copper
Top Layer:
  region net B+: 5473.57,6971.38 5473.57,6991.38 5476.85,6991.66 5479.79,6992.44 5482.47,6993.66 5484.96,6995.24 5487.33,6997.11 5489.68,6999.2 5494.57,7003.74 5494.57,6959.02 5489.68,6963.56 5487.33,6965.64 5484.96,6967.52 5482.47,6969.1 5479.79,6970.32 5476.85,6971.1
  region net +3.3V: 4284.29,4357.6 4298.43,4343.46 4296.58,4341.27 4295.17,4338.92 4294.13,4336.41 4293.41,4333.78 4292.92,4331.03 4292.61,4328.2 4292.24,4322.36 4263.19,4351.41 4269.03,4351.78 4271.86,4352.09 4274.61,4352.58 4277.24,4353.3 4279.74,4354.34 4282.1,4355.75
  region net RXD: 4073.54,4343.46 4087.69,4357.6 4089.87,4355.75 4092.23,4354.34 4094.74,4353.3 4097.37,4352.58 4100.11,4352.09 4102.94,4351.78 4108.78,4351.41 4079.73,4322.36 4079.37,4328.2 4079.05,4331.03 4078.57,4333.78 4077.84,4336.41 4076.81,4338.92 4075.4,4341.27
  region net EN: 3994.8,4343.46 4008.95,4357.6 4011.13,4355.75 4013.49,4354.34 4016,4353.3 4018.63,4352.58 4021.37,4352.09 4024.2,4351.78 4030.04,4351.41 4000.99,4322.36 4000.63,4328.2 4000.31,4331.03 3999.83,4333.78 3999.1,4336.41 3998.07,4338.92 3996.66,4341.27
  region net KEY_BACK: 3812.44,6499.25 3812.44,6479.25 ccw(c3812.44,6441.75) 3782.44,6464.25 3782.44,6514.25 ccw(c3812.44,6536.75)
  region net KEY_BACK: 4244.57,6479.25 4244.57,6499.25 ccw(c4244.57,6536.75) 4274.57,6514.25 4274.57,6464.25 ccw(c4244.57,6441.75)
  region net KEY_BACK: 4339.93,6539.23 4344.23,6515.24 ccw(c4386.66,6483.42) 4333.63,6483.42 4308.11,6528.62 ccw(c4308.11,6581.66)
  region net KEY_MENU: 4622.96,6676.45 4614.03,6713.66 ccw(c4680.07,6779.7) 4638.74,6695.95 4638.74,6649.8 ccw(c4578.8,6632.29)
  region net KEY_MENU: 4686.07,6606.89 4666.07,6606.89 ccw(c4628.57,6606.89) 4651.07,6636.89 4701.07,6636.89 ccw(c4723.57,6606.89)
  region net KEY_MENU: 4666.07,6174.76 4686.07,6174.76 ccw(c4723.57,6174.76) 4701.07,6144.76 4651.07,6144.76 ccw(c4628.57,6174.76)
  region net KEY_ENTER: 4846.07,6557.48 4866.07,6557.48 ccw(c4901.33,6557.48) 4881.07,6528.62 4831.07,6528.62 ccw(c4810.81,6557.48)
  region net KEY_ENTER: 4914.81,6499.25 4914.81,6479.25 ccw(c4914.81,6441.75) 4884.81,6464.25 4884.81,6514.25 ccw(c4914.81,6536.75)
  region net KEY_ENTER: 5346.93,6479.25 5346.93,6499.25 ccw(c5346.93,6536.75) 5376.93,6514.25 5376.93,6464.25 ccw(c5346.93,6441.75)
  region net KEY_1: 4136.93,6055.71 4116.93,6055.71 ccw(c4079.43,6055.71) 4101.93,6085.71 4151.93,6085.71 ccw(c4174.43,6055.71)
  region net KEY_1: 4196.3,6125.24 4196.3,6105.24 ccw(c4196.3,6067.74) 4166.3,6090.24 4166.3,6140.24 ccw(c4196.3,6162.74)
  region net KEY_1: 4116.93,5623.58 4136.93,5623.58 ccw(c4174.43,5623.58) 4151.93,5593.58 4101.93,5593.58 ccw(c4079.43,5623.58)
  region net KEY_2: 4363.63,5948.07 4363.63,5928.07 ccw(c4363.63,5890.57) 4333.63,5913.07 4333.63,5963.07 ccw(c4363.63,5985.57)
  region net KEY_2: 4795.75,5928.07 4795.75,5948.07 ccw(c4795.75,5985.57) 4825.75,5963.07 4825.75,5913.07 ccw(c4795.75,5890.57)
  region net KEY_3: 5239.3,6055.71 5219.3,6055.71 ccw(c5181.8,6055.71) 5204.3,6085.71 5254.3,6085.71 ccw(c5276.8,6055.71)
  region net KEY_3: 5219.3,5623.58 5239.3,5623.58 ccw(c5276.8,5623.58) 5254.3,5593.58 5204.3,5593.58 ccw(c5181.8,5623.58)
  region net KEY_4: 3812.44,5396.89 3812.44,5376.89 ccw(c3812.44,5339.39) 3782.44,5361.89 3782.44,5411.89 ccw(c3812.44,5434.39)
  region net KEY_4: 4256.07,5376.89 4256.07,5396.89 ccw(c4256.07,5415.8) 4274.57,5411.89 4274.57,5361.89 ccw(c4256.07,5357.98)
  region net KEY_5: 4688.11,5504.53 4668.11,5504.53 ccw(c4630.61,5504.53) 4653.11,5534.53 4703.11,5534.53 ccw(c4725.61,5504.53)
  region net KEY_5: 4668.11,5619.84 4688.11,5619.84 ccw(c4718.6,5619.84) 4703.11,5593.58 4653.11,5593.58 ccw(c4637.62,5619.84)
  region net KEY_5: 4668.11,5072.4 4688.11,5072.4 ccw(c4725.61,5072.4) 4703.11,5042.4 4653.11,5042.4 ccw(c4630.61,5072.4)
  region net KEY_6: 4815.15,5412.88 4819.44,5436.87 ccw(c4851.26,5479.29) 4851.26,5426.26 4825.75,5381.06 ccw(c4772.72,5381.06)
  region net KEY_6: 4914.81,5396.89 4914.81,5376.89 ccw(c4914.81,5339.39) 4884.81,5361.89 4884.81,5411.89 ccw(c4914.81,5434.39)
  region net KEY_6: 5346.93,5376.89 5346.93,5396.89 ccw(c5346.93,5434.39) 5376.93,5411.89 5376.93,5361.89 ccw(c5346.93,5339.39)
  region net KEY_7: 4136.93,4953.35 4116.93,4953.35 ccw(c4079.43,4953.35) 4101.93,4983.35 4151.93,4983.35 ccw(c4174.43,4953.35)
  region net KEY_7: 4116.93,4521.22 4136.93,4521.22 ccw(c4174.43,4521.22) 4151.93,4491.22 4101.93,4491.22 ccw(c4079.43,4521.22)
  region net KEY_8: 4363.63,4845.71 4363.63,4825.71 ccw(c4363.63,4788.21) 4333.63,4810.71 4333.63,4860.71 ccw(c4363.63,4883.21)
  region net KEY_8: 4795.75,4825.71 4795.75,4845.71 ccw(c4795.75,4883.21) 4825.75,4860.71 4825.75,4810.71 ccw(c4795.75,4788.21)
  region net KEY_9: 5239.3,4953.35 5219.3,4953.35 ccw(c5181.8,4953.35) 5204.3,4983.35 5254.3,4983.35 ccw(c5276.8,4953.35)
  region net KEY_9: 5219.3,4521.22 5239.3,4521.22 ccw(c5276.8,4521.22) 5254.3,4491.22 5204.3,4491.22 ccw(c5181.8,4521.22)
  region net I2C_SCL: 4639.69,8038 4619.69,8038 4619.6,8040.02 4619.35,8041.88 4618.95,8043.61 4618.4,8045.21 4617.73,8046.72 4616.93,8048.13 4615.02,8050.78 4612.76,8053.3 4610.23,8055.82 4607.53,8058.48 4604.74,8061.43 4654.63,8061.43 4651.84,8058.48 4649.14,8055.82 4646.62,8053.3 4644.36,8050.78 4642.45,8048.13 4641.65,8046.72 4640.97,8045.21 4640.43,8043.61 4640.02,8041.88 4639.77,8040.02
  region net I2C_SDA: 4739.69,8038 4719.69,8038 4719.6,8040.02 4719.35,8041.88 4718.95,8043.61 4718.4,8045.21 4717.73,8046.72 4716.93,8048.13 4715.02,8050.78 4712.76,8053.3 4710.23,8055.82 4707.53,8058.48 4704.74,8061.43 4754.63,8061.43 4751.84,8058.48 4749.14,8055.82 4746.62,8053.3 4744.36,8050.78 4742.45,8048.13 4741.65,8046.72 4740.97,8045.21 4740.43,8043.61 4740.02,8041.88 4739.77,8040.02
  region net $1N15750: 4806.22,7680.98 4786.22,7680.98 4786.13,7683.19 4785.86,7685.21 4785.41,7687.06 4784.81,7688.76 4784.07,7690.34 4783.2,7691.82 4781.1,7694.56 4778.61,7697.15 4775.84,7699.77 4772.88,7702.59 4769.81,7705.79 4822.63,7705.79 4819.57,7702.59 4816.61,7699.77 4813.84,7697.15 4811.35,7694.56 4809.25,7691.82 4808.38,7690.34 4807.64,7688.76 4807.04,7687.06 4806.59,7685.21 4806.32,7683.19
  region net $1N15750: 5003.81,7355.6 5017.95,7369.74 5019.88,7367.93 5021.81,7366.32 5025.4,7363.71 5028.16,7361.92 5029.56,7360.97 5012.58,7343.99 5011.62,7345.39 5009.84,7348.15 5007.23,7351.73 5005.62,7353.67
  region net I2C_SDA: 4719.69,7488.27 4739.69,7488.27 4739.8,7485.88 4740.09,7483.99 4740.52,7482.43 4741.03,7481.05 4742.13,7478.12 4742.62,7476.24 4743,7473.86 4719.14,7471.1 4718.96,7475.31 4719.18,7479.67 4719.51,7484.04
  region net I2C_SCL: 4505.48,7387.48 4505.48,7367.48 4502.83,7367.39 4500.33,7367.17 4495.94,7366.48 4492.73,7365.79 4491.07,7365.47 4491.07,7389.49 4492.73,7389.17 4495.94,7388.48 4500.33,7387.79 4502.83,7387.57
  region net EN: 3961.66,7487.48 3961.66,7507.48 3964.3,7507.57 3966.81,7507.79 3971.19,7508.48 3974.41,7509.17 3976.07,7509.49 3976.07,7485.47 3974.41,7485.79 3971.19,7486.48 3966.81,7487.17 3964.3,7487.39
  region net +3.3V: 5501.07,6203.07 5481.07,6203.07 5480.98,6205.72 5480.75,6208.22 5480.06,6212.6 5479.37,6215.82 5479.06,6217.48 5503.07,6217.48 5502.76,6215.82 5502.07,6212.6 5501.38,6208.22 5501.15,6205.72
  region net +3.3V: 5494.19,6234.74 5508.33,6220.6 5506.52,6218.67 5504.91,6216.73 5502.3,6213.15 5500.51,6210.39 5499.56,6208.99 5482.58,6225.97 5483.97,6226.92 5486.74,6228.71 5490.32,6231.32 5492.25,6232.93
  region net TXD: 4002.36,6675.22 3988.22,6689.36 3990.03,6691.3 3991.64,6693.23 3994.25,6696.81 3996.04,6699.58 3996.99,6700.97 4013.97,6683.99 4012.57,6683.04 4009.81,6681.25 4006.22,6678.64 4004.29,6677.03
  region net TXD: 3666.07,4471.89 3686.07,4471.89 3686.15,4469.24 3686.38,4466.74 3687.07,4462.36 3687.76,4459.14 3688.07,4457.48 3664.06,4457.48 3664.37,4459.14 3665.06,4462.36 3665.75,4466.74 3665.98,4469.24
  region net RXD: 4052.36,6675.22 4038.22,6689.36 4040.03,6691.3 4041.64,6693.23 4044.25,6696.81 4046.04,6699.58 4046.99,6700.97 4063.97,6683.99 4062.57,6683.04 4059.81,6681.25 4056.22,6678.64 4054.29,6677.03
  region net 433_TX: 5124.19,7519.74 5138.33,7505.6 5136.52,7503.67 5134.91,7501.73 5132.3,7498.15 5130.51,7495.39 5129.56,7493.99 5112.58,7510.97 5113.97,7511.92 5116.74,7513.71 5120.32,7516.32 5122.25,7517.93
  region net 433_TX: 5199.12,7895.22 5184.97,7909.36 5186.78,7911.3 5188.39,7913.23 5191,7916.81 5192.79,7919.58 5193.74,7920.97 5210.73,7903.99 5209.33,7903.04 5206.57,7901.25 5202.98,7898.64 5201.05,7897.03
  region net KEY_9: 4955.48,4937.48 4955.48,4917.48 4952.83,4917.39 4950.33,4917.17 4945.94,4916.48 4942.73,4915.79 4941.07,4915.47 4941.07,4939.49 4942.73,4939.17 4945.94,4938.48 4950.33,4937.79 4952.83,4937.57
  region net KEY_7: 4202.95,4905.22 4188.81,4919.36 4190.62,4921.3 4192.23,4923.23 4194.84,4926.81 4196.62,4929.58 4197.58,4930.97 4214.56,4913.99 4213.16,4913.04 4210.4,4911.25 4206.81,4908.64 4204.88,4907.03
  region net KEY_6: 4793.33,5462.98 4779.19,5448.84 4775.79,5451.9 4772.89,5454.13 4770.07,5456.42 4768.56,5457.88 4766.92,5459.71 4785.22,5475.25 4786.72,5473.33 4787.76,5471.7 4789.11,5468.97 4789.73,5467.67 4790.54,5466.31 4791.68,5464.77
  region net KEY_3: 4843.33,6064.36 4829.19,6050.22 4827.25,6052.03 4825.32,6053.64 4821.74,6056.25 4818.97,6058.04 4817.58,6058.99 4834.56,6075.97 4835.51,6074.58 4837.3,6071.81 4839.91,6068.23 4841.52,6066.3
  region net KEY_2: 4591.07,6038.07 4571.07,6038.07 4570.98,6040.72 4570.75,6043.22 4570.06,6047.6 4569.37,6050.82 4569.06,6052.48 4593.07,6052.48 4592.76,6050.82 4592.07,6047.6 4591.38,6043.22 4591.15,6040.72
  region net KEY_1: 4302.95,6155.22 4288.81,6169.36 4290.62,6171.3 4292.23,6173.23 4294.84,6176.81 4296.62,6179.58 4297.58,6180.97 4314.56,6163.99 4313.16,6163.04 4310.4,6161.25 4306.81,6158.64 4304.88,6157.03
  region net KEY_ENTER: 4866.07,6543.07 4846.07,6543.07 4845.98,6545.72 4845.75,6548.22 4845.06,6552.6 4844.37,6555.82 4844.06,6557.48 4868.07,6557.48 4867.76,6555.82 4867.07,6552.6 4866.38,6548.22 4866.15,6545.72
  region net KEY_MENU: 4511.07,6833.07 4491.07,6833.07 4490.98,6835.72 4490.75,6838.22 4490.06,6842.6 4489.37,6845.82 4489.06,6847.48 4513.07,6847.48 4512.76,6845.82 4512.07,6842.6 4511.38,6838.22 4511.15,6835.72
  region net KEY_5: 4472.74,5839.36 4458.6,5825.22 4456.66,5827.03 4454.73,5828.64 4451.15,5831.25 4448.38,5833.04 4446.99,5833.99 4463.97,5850.97 4464.92,5849.58 4466.71,5846.81 4469.32,5843.23 4470.93,5841.3
  region net KEY_8: 4422.25,4845.71 4418.7,4825.71 4411.48,4825.45 4407.59,4825.39 4404.3,4825.6 4407.84,4849.36 4409.96,4848.94 4411.8,4848.4 4415.02,4847.19 4418.25,4846.15 4420.1,4845.83
  region net KEY_8: 4387.43,4825.71 4383.88,4845.71 4386.28,4845.83 4388.82,4846.15 4394.11,4847.19 4399.4,4848.4 4404.3,4849.36 4407.84,4825.6 4405.68,4825.39 4403.19,4825.29 4397.65,4825.36
  region net KEY_BACK: 4366.07,6578.07 4346.07,6578.07 4345.98,6580.72 4345.75,6583.22 4345.06,6587.6 4344.37,6590.82 4344.06,6592.48 4368.07,6592.48 4367.76,6590.82 4367.07,6587.6 4366.38,6583.22 4366.15,6580.72
  region net KEY_4: 4241.66,5376.89 4240.48,5396.89 4242.9,5396.99 4244.79,5397.24 4247.69,5398.05 4250.58,5398.92 4252.47,5399.26 4254.89,5399.47 4256.07,5375.49 4253.67,5375.45 4251.79,5375.56 4248.87,5376.06 4245.95,5376.62 4244.06,5376.82
  region net KEY_4: 4270.48,5396.89 4270.48,5376.89 4267.88,5376.81 4265.84,5376.62 4262.68,5376.04 4259.52,5375.54 4257.48,5375.44 4254.89,5375.49 4256.07,5399.47 4258.49,5399.26 4260.38,5398.92 4263.27,5398.05 4266.17,5397.24 4268.06,5396.99
  region net B+: 5055.48,6991.38 5055.48,6971.38 5052.83,6971.29 5050.33,6971.06 5045.94,6970.37 5042.73,6969.68 5041.07,6969.37 5041.07,6993.39 5042.73,6993.07 5045.94,6992.38 5050.33,6991.69 5052.83,6991.46
  region net +3.3V: 5381.07,7758.07 5361.07,7758.07 5360.98,7760.72 5360.75,7763.22 5360.06,7767.6 5359.37,7770.82 5359.06,7772.48 5383.07,7772.48 5382.76,7770.82 5382.07,7767.6 5381.38,7763.22 5381.15,7760.72
  region net KEY_9: 5159.3,4937.48 ccw(c5159.3,5037.48) 5219.3,4957.48 5229.3,4927.08 5219.3,4897.48 ccw(c5159.3,4817.48) 5159.3,4917.48
  region net KEY_3: 5159.3,6022.48 ccw(c5159.3,6122.48) 5219.3,6042.48 5229.3,6012.48
  region net KEY_2: 4571.07,6008.07 cw(c4471.07,6008.07) 4551.07,5948.07 4586.07,5938.07 4611.07,5948.07 cw(c4691.07,6008.07) 4591.07,6008.07
  region net KEY_7: 4171.07,4897.48 cw(c4171.07,4936.61) 4136.93,4917.48 4126.93,4887.48 4136.93,4857.48 cw(c4171.07,4838.35) 4171.07,4877.48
